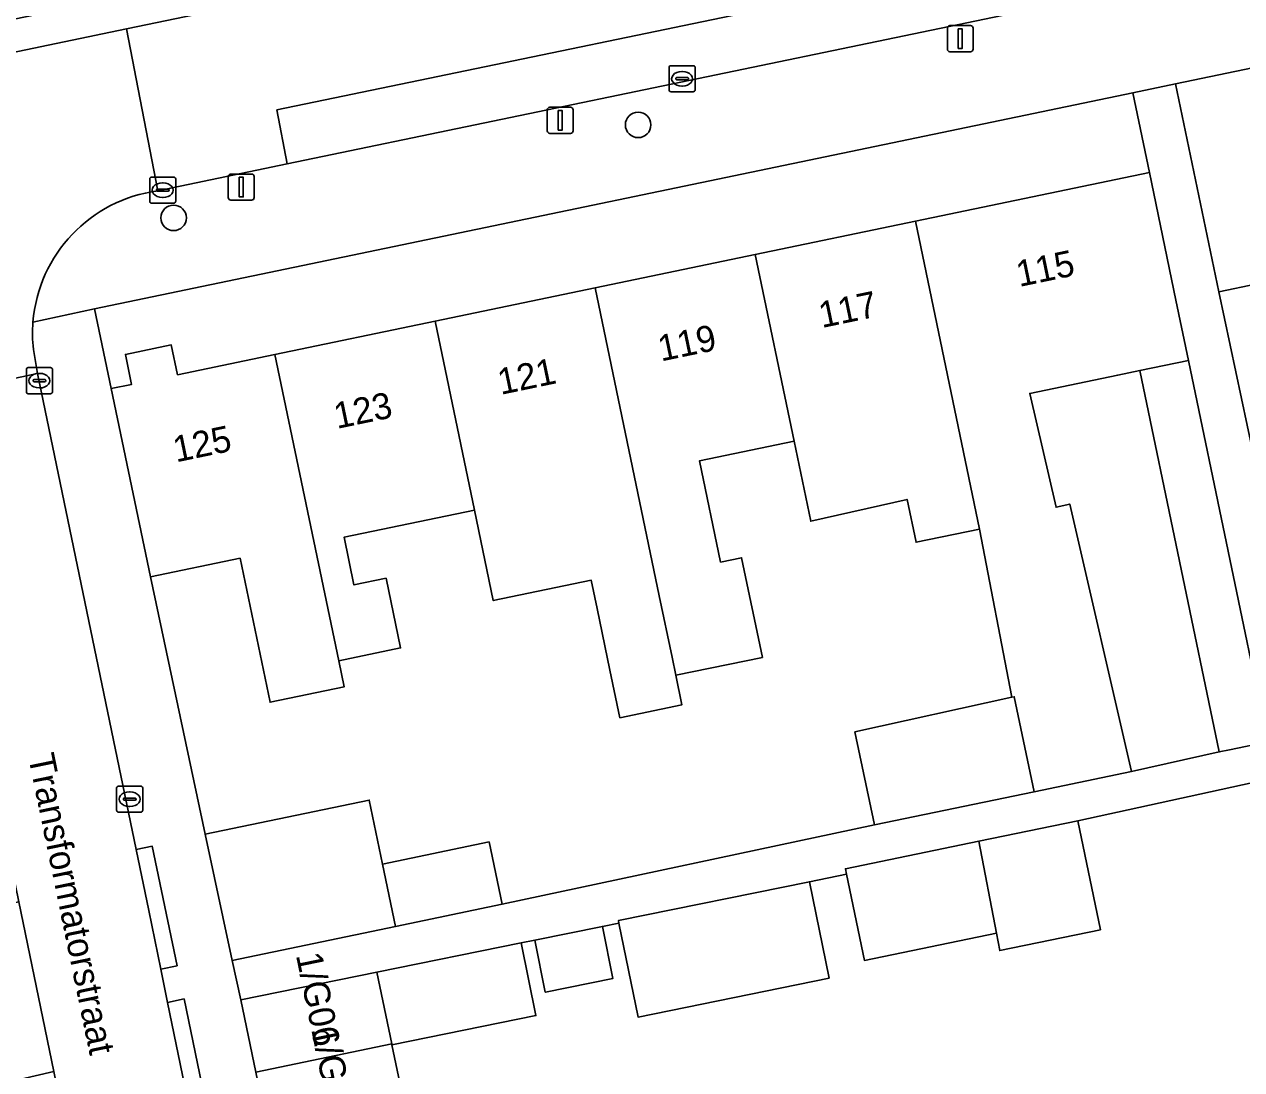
# Model space of a CAD drawing. Extents: x 162989 to 165008, y 383432 to 384338.
# Drawn here: x 163580.92 to 163627.57, y 384033.07 to 384073.15 of the extents above; entities that cross this region are included whole.
import ezdxf

# ---------------------------------------------------------------- set-up
doc = ezdxf.new("R2010")
doc.units = 0
for name, color, linetype in [('IMGEO_Boom', 7, 'Continuous'), ('IMGEO_Erf', 7, 'Continuous'), ('IMGEO_Groenvoorziening', 7, 'Continuous'), ('IMGEO_Kolk', 7, 'Continuous'), ('IMGEO_Lichtmast', 7, 'Continuous'), ('IMGEO_Muur', 7, 'Continuous'), ('IMGEO_Openbare_ruimte_label', 7, 'Continuous'), ('IMGEO_Pand', 7, 'Continuous'), ('IMGEO_Pand_nummerreeks', 7, 'Continuous'), ('IMGEO_Parkeervlak_gesloten', 7, 'Continuous'), ('IMGEO_Rijbaan_lokaal_gesloten', 7, 'Continuous'), ('IMGEO_Rijbaan_lokaal_open', 7, 'Continuous'), ('IMGEO_Voetpad_open', 7, 'Continuous')]:
    doc.layers.add(name, color=color, linetype=linetype)

msp = doc.modelspace()

# ---------------------------------------------------------------- linework, layer by layer
at = {"layer": 'IMGEO_Boom'}
for centre in [(163604.444, 384069.294), (163586.64, 384065.728)]:
    msp.add_circle(centre, 0.489, dxfattribs=at)
at = {"layer": 'IMGEO_Erf'}
for points in [[(163659.843, 384072.857), (163662.816, 384073.476), (163662.616, 384074.437), (163665.063, 384074.949), (163665.263, 384073.985), (163666.126, 384074.165), (163666.339, 384073.14), (163669.273, 384073.751), (163668.011, 384079.81), (163625.04, 384070.863), (163626.7, 384062.893), (163629.637, 384063.504), (163629.026, 384066.441), (163635.305, 384067.748), (163641.439, 384069.025), (163642.135, 384069.17), (163641.933, 384070.139), (163644.293, 384070.631), (163644.494, 384069.661), (163647.574, 384070.303), (163653.707, 384071.579)], [(163623.4, 384070.522), (163583.605, 384062.236), (163584.246, 384059.183), (163585.029, 384059.346), (163584.791, 384060.491), (163586.553, 384060.858), (163586.791, 384059.713), (163590.526, 384060.49), (163596.662, 384061.768), (163602.797, 384063.045), (163608.933, 384064.322), (163615.068, 384065.599), (163624.036, 384067.466)], [(163623.669, 384059.875), (163622.828, 384059.7), (163619.451, 384058.997), (163620.46, 384054.633), (163620.987, 384054.754), (163623.355, 384044.505), (163626.714, 384045.25)], [(163602.873, 384050.747), (163602.646, 384051.837), (163598.891, 384051.056), (163598.17, 384054.521), (163593.174, 384053.481), (163593.554, 384051.653), (163594.785, 384051.909), (163595.341, 384049.239), (163592.972, 384048.744), (163593.179, 384047.749), (163590.336, 384047.157), (163589.186, 384052.68), (163585.749, 384051.964), (163587.856, 384042.101), (163594.14, 384043.409), (163594.652, 384040.952), (163598.731, 384041.801), (163599.228, 384039.412), (163613.497, 384042.453), (163612.754, 384046.021), (163618.763, 384047.349), (163617.523, 384053.796), (163615.094, 384053.291), (163614.752, 384054.934), (163611.06, 384054.099), (163610.421, 384057.17), (163606.798, 384056.416), (163607.606, 384052.532), (163608.411, 384052.699), (163609.206, 384048.879), (163605.887, 384048.189), (163606.122, 384047.059), (163603.743, 384046.564), (163603.363, 384048.389)]]:
    msp.add_lwpolyline(points, close=True, dxfattribs=at)
msp.add_lwpolyline([(163629.536, 384044.408), (163621.297, 384042.615), (163622.161, 384038.437), (163618.3, 384037.633), (163618.172, 384038.306), (163613.117, 384037.26), (163612.432, 384040.571), (163611.007, 384040.276), (163611.76, 384036.579), (163604.439, 384035.087), (163603.705, 384038.688), (163603.073, 384038.559), (163603.477, 384036.571), (163600.895, 384036.046), (163600.884, 384036.044), (163600.48, 384038.032), (163599.962, 384037.927), (163600.527, 384035.142), (163595.008, 384034.021), (163595.573, 384031.285)], dxfattribs=at)
at = {"layer": 'IMGEO_Groenvoorziening'}
msp.add_lwpolyline([(163830.895, 384125.387), (163651.736, 384088.019), (163459.771, 384048.486), (163422.158, 384040.849), (163419.713, 384040.294), (163409.522, 384037.258), (163408.734, 384037.023), (163409.808, 384036.105), (163410.773, 384036.455), (163412.582, 384037.103), (163414.405, 384037.712), (163416.239, 384038.284), (163418.085, 384038.817), (163419.942, 384039.312), (163421.809, 384039.768), (163423.331, 384040.11), (163470.865, 384049.76), (163474.78, 384050.554), (163569.015, 384069.685), (163584.838, 384072.976), (163644.593, 384085.348), (163648.507, 384086.167), (163682.411, 384093.294), (163707.965, 384098.574)], dxfattribs=at)
at = {"layer": 'IMGEO_Kolk'}
for p, q in [((163605.629, 384070.638), (163605.629, 384071.49)), ((163605.704, 384071.564), (163606.556, 384071.564)), ((163606.117, 384071.344), (163606.142, 384071.344)), ((163606.63, 384071.49), (163606.63, 384070.638)), ((163605.888, 384071.058), (163605.888, 384071.07)), ((163606.326, 384071.021), (163605.928, 384071.021)), ((163605.931, 384071.107), (163606.329, 384071.107)), ((163606.14, 384070.784), (163606.115, 384070.784)), ((163606.372, 384071.07), (163606.372, 384071.058)), ((163606.556, 384070.564), (163605.704, 384070.564)), ((163585.724, 384066.366), (163585.724, 384067.218)), ((163585.799, 384067.292), (163586.651, 384067.292)), ((163586.212, 384067.072), (163586.237, 384067.072)), ((163586.725, 384067.218), (163586.725, 384066.366)), ((163585.983, 384066.786), (163585.983, 384066.798)), ((163586.421, 384066.749), (163586.023, 384066.749)), ((163586.026, 384066.835), (163586.424, 384066.835)), ((163586.235, 384066.512), (163586.21, 384066.512)), ((163586.467, 384066.798), (163586.467, 384066.786)), ((163586.651, 384066.292), (163585.799, 384066.292)), ((163581.073, 384059.988), (163581.925, 384059.988)), ((163580.998, 384059.062), (163580.998, 384059.914)), ((163581.257, 384059.482), (163581.257, 384059.494)), ((163581.3, 384059.531), (163581.698, 384059.531)), ((163581.486, 384059.768), (163581.511, 384059.768)), ((163581.741, 384059.494), (163581.741, 384059.482)), ((163581.999, 384059.914), (163581.999, 384059.062)), ((163581.695, 384059.445), (163581.297, 384059.445)), ((163581.509, 384059.208), (163581.484, 384059.208)), ((163581.925, 384058.988), (163581.073, 384058.988)), ((163584.457, 384043.016), (163584.457, 384043.868)), ((163584.532, 384043.942), (163585.384, 384043.942)), ((163584.945, 384043.722), (163584.97, 384043.722)), ((163585.458, 384043.868), (163585.458, 384043.016)), ((163584.716, 384043.436), (163584.716, 384043.448)), ((163585.154, 384043.399), (163584.756, 384043.399)), ((163584.759, 384043.485), (163585.157, 384043.485)), ((163585.2, 384043.448), (163585.2, 384043.436)), ((163585.384, 384042.942), (163584.532, 384042.942)), ((163584.968, 384043.162), (163584.943, 384043.162))]:
    msp.add_line(p, q, dxfattribs=at)
for points in [[(163605.629, 384070.638), (163605.629, 384071.49)], [(163605.704, 384071.564), (163606.556, 384071.564)], [(163606.63, 384071.49), (163606.63, 384070.638)], [(163606.556, 384070.564), (163605.704, 384070.564)], [(163585.724, 384066.366), (163585.724, 384067.218)], [(163585.799, 384067.292), (163586.651, 384067.292)], [(163586.725, 384067.218), (163586.725, 384066.366)], [(163586.651, 384066.292), (163585.799, 384066.292)], [(163581.073, 384059.988), (163581.925, 384059.988)], [(163580.998, 384059.062), (163580.998, 384059.914)], [(163581.999, 384059.914), (163581.999, 384059.062)], [(163581.925, 384058.988), (163581.073, 384058.988)], [(163584.457, 384043.016), (163584.457, 384043.868)], [(163584.532, 384043.942), (163585.384, 384043.942)], [(163585.458, 384043.868), (163585.458, 384043.016)], [(163585.384, 384042.942), (163584.532, 384042.942)]]:
    msp.add_lwpolyline(points, dxfattribs=at)
for centre, radius, start, end in [((163605.706, 384071.488), 0.0765, 91.552, 178.448), ((163605.706, 384071.488), 0.0765, 91.552, 178.448), ((163606.554, 384071.488), 0.0765, 1.552, 88.448), ((163606.554, 384071.488), 0.0765, 1.552, 88.448), ((163605.928, 384071.067), 0.0403, 85.8775, 175.7526), ((163605.925, 384071.057), 0.0366, 178.938, 274.7102), ((163606.329, 384071.064), 0.043, 264.8664, 352.4533), ((163606.333, 384071.069), 0.0386, 1.7309, 96.639), ((163605.706, 384070.64), 0.0765, 181.552, 268.448), ((163605.706, 384070.64), 0.0765, 181.552, 268.448), ((163606.554, 384070.64), 0.0765, 271.552, 358.448), ((163606.554, 384070.64), 0.0765, 271.552, 358.448), ((163585.801, 384067.216), 0.0765, 91.552, 178.448), ((163585.801, 384067.216), 0.0765, 91.552, 178.448), ((163586.649, 384067.216), 0.0765, 1.552, 88.448), ((163586.649, 384067.216), 0.0765, 1.552, 88.448), ((163586.023, 384066.795), 0.0403, 85.8775, 175.7526), ((163586.02, 384066.785), 0.0366, 178.938, 274.7102), ((163586.424, 384066.792), 0.043, 264.8664, 352.4533), ((163586.428, 384066.797), 0.0386, 1.7309, 96.639), ((163585.801, 384066.368), 0.0765, 181.552, 268.448), ((163585.801, 384066.368), 0.0765, 181.552, 268.448), ((163586.649, 384066.368), 0.0765, 271.552, 358.448), ((163586.649, 384066.368), 0.0765, 271.552, 358.448), ((163581.075, 384059.912), 0.0765, 91.552, 178.448), ((163581.075, 384059.912), 0.0765, 91.552, 178.448), ((163581.923, 384059.912), 0.0765, 1.552, 88.448), ((163581.923, 384059.912), 0.0765, 1.552, 88.448), ((163581.297, 384059.491), 0.0403, 85.8775, 175.7526), ((163581.702, 384059.493), 0.0386, 1.7309, 96.639), ((163581.075, 384059.064), 0.0765, 181.552, 268.448), ((163581.075, 384059.064), 0.0765, 181.552, 268.448), ((163581.294, 384059.481), 0.0366, 178.938, 274.7102), ((163581.698, 384059.488), 0.043, 264.8664, 352.4533), ((163581.923, 384059.064), 0.0765, 271.552, 358.448), ((163581.923, 384059.064), 0.0765, 271.552, 358.448), ((163584.534, 384043.866), 0.0765, 91.552, 178.448), ((163584.534, 384043.866), 0.0765, 91.552, 178.448), ((163585.382, 384043.866), 0.0765, 1.552, 88.448), ((163585.382, 384043.866), 0.0765, 1.552, 88.448), ((163584.756, 384043.445), 0.0403, 85.8775, 175.7526), ((163584.753, 384043.435), 0.0366, 178.938, 274.7102), ((163585.157, 384043.442), 0.043, 264.8664, 352.4533), ((163585.161, 384043.447), 0.0386, 1.7309, 96.639), ((163584.534, 384043.018), 0.0765, 181.552, 268.448), ((163584.534, 384043.018), 0.0765, 181.552, 268.448), ((163585.382, 384043.018), 0.0765, 271.552, 358.448), ((163585.382, 384043.018), 0.0765, 271.552, 358.448)]:
    msp.add_arc(centre, radius, start, end, dxfattribs=at)
for centre, major_axis, ratio, start_param, end_param in [((163606.116, 384071.064), (-0.387, 0.002), 0.722429, 4.712389, 7.853982), ((163606.141, 384071.064), (-0.39, 0.002), 0.717154, 1.570796, 4.712389), ((163586.211, 384066.792), (-0.387, 0.002), 0.722429, 4.712389, 7.853982), ((163586.236, 384066.792), (-0.39, 0.002), 0.717154, 1.570796, 4.712389), ((163581.485, 384059.488), (-0.387, 0.002), 0.722429, 4.712389, 7.853982), ((163581.51, 384059.488), (-0.39, 0.002), 0.717154, 1.570796, 4.712389), ((163584.944, 384043.442), (-0.387, 0.002), 0.722429, 4.712389, 7.853982), ((163584.969, 384043.442), (-0.39, 0.002), 0.717154, 1.570796, 4.712389)]:
    msp.add_ellipse(centre, major_axis=major_axis, ratio=ratio, start_param=start_param, end_param=end_param, dxfattribs=at)
at = {"layer": 'IMGEO_Lichtmast'}
for p, q in [((163616.395, 384073.1), (163617.185, 384073.1)), ((163617.185, 384073.1), (163616.395, 384073.1)), ((163616.295, 384072.2), (163616.295, 384073)), ((163616.295, 384073), (163616.295, 384072.2)), ((163617.285, 384073), (163617.285, 384072.2)), ((163617.285, 384072.2), (163617.285, 384073)), ((163617.185, 384072.1), (163616.395, 384072.1)), ((163616.395, 384072.1), (163617.185, 384072.1)), ((163600.963, 384069.068), (163600.963, 384069.868)), ((163600.963, 384069.868), (163600.963, 384069.068)), ((163601.063, 384069.968), (163601.853, 384069.968)), ((163601.853, 384069.968), (163601.063, 384069.968)), ((163601.953, 384069.868), (163601.953, 384069.068)), ((163601.953, 384069.068), (163601.953, 384069.868)), ((163601.853, 384068.968), (163601.063, 384068.968)), ((163601.063, 384068.968), (163601.853, 384068.968)), ((163588.738, 384066.509), (163588.738, 384067.309)), ((163588.738, 384067.309), (163588.738, 384066.509)), ((163588.838, 384067.409), (163589.628, 384067.409)), ((163589.628, 384067.409), (163588.838, 384067.409)), ((163589.728, 384067.309), (163589.728, 384066.509)), ((163589.728, 384066.509), (163589.728, 384067.309)), ((163589.628, 384066.409), (163588.838, 384066.409)), ((163588.838, 384066.409), (163589.628, 384066.409))]:
    msp.add_line(p, q, dxfattribs=at)
for points in [[(163616.715, 384072.975), (163616.865, 384072.975), (163616.865, 384072.225), (163616.715, 384072.225), (163616.715, 384072.975)], [(163601.383, 384069.843), (163601.533, 384069.843), (163601.533, 384069.093), (163601.383, 384069.093), (163601.383, 384069.843)], [(163589.158, 384067.284), (163589.308, 384067.284), (163589.308, 384066.534), (163589.158, 384066.534), (163589.158, 384067.284)]]:
    msp.add_lwpolyline(points, dxfattribs=at)
for centre, start, end in [((163616.395, 384073), 90, 180), ((163616.395, 384073), 90, 180), ((163617.185, 384073), 0, 90), ((163617.185, 384073), 360, 90), ((163616.395, 384072.2), 180, 270), ((163616.395, 384072.2), 180, 270), ((163617.185, 384072.2), 270, 0), ((163617.185, 384072.2), 270, 0), ((163601.063, 384069.868), 90, 180), ((163601.063, 384069.868), 90, 180), ((163601.853, 384069.868), 0, 90), ((163601.853, 384069.868), 360, 90), ((163601.063, 384069.068), 180, 270), ((163601.063, 384069.068), 180, 270), ((163601.853, 384069.068), 270, 0), ((163601.853, 384069.068), 270, 0), ((163588.838, 384067.309), 90, 180), ((163588.838, 384067.309), 90, 180), ((163589.628, 384067.309), 0, 90), ((163589.628, 384067.309), 360, 90), ((163588.838, 384066.509), 180, 270), ((163588.838, 384066.509), 180, 270), ((163589.628, 384066.509), 270, 0), ((163589.628, 384066.509), 270, 0)]:
    msp.add_arc(centre, 0.1, start, end, dxfattribs=at)
at = {"layer": 'IMGEO_Muur'}
msp.add_lwpolyline([(163585.749, 384051.964), (163587.856, 384042.101)], dxfattribs=at)
at = {"layer": 'IMGEO_Pand'}
for points in [[(163625.055, 384062.571), (163624.036, 384067.466), (163615.068, 384065.599), (163617.523, 384053.796), (163618.763, 384047.349), (163618.859, 384047.37), (163619.617, 384043.727), (163623.355, 384044.505), (163620.987, 384054.754), (163620.46, 384054.633), (163619.451, 384058.997), (163622.828, 384059.7), (163623.669, 384059.875), (163625.535, 384060.264)], [(163635.305, 384067.748), (163629.026, 384066.441), (163629.637, 384063.504), (163626.7, 384062.893), (163628.216, 384055.732), (163634.948, 384057.032), (163635.285, 384055.287), (163637.792, 384055.812)], [(163608.933, 384064.322), (163610.421, 384057.17), (163611.06, 384054.099), (163614.752, 384054.934), (163615.094, 384053.291), (163617.523, 384053.796), (163615.068, 384065.599)], [(163608.933, 384064.322), (163602.797, 384063.045), (163605.252, 384051.242), (163605.742, 384048.884), (163605.887, 384048.189), (163609.206, 384048.879), (163608.411, 384052.699), (163607.606, 384052.532), (163606.798, 384056.416), (163610.421, 384057.17)], [(163602.797, 384063.045), (163596.662, 384061.768), (163598.17, 384054.521), (163598.891, 384051.056), (163602.646, 384051.837), (163602.873, 384050.747), (163603.363, 384048.389), (163603.743, 384046.564), (163606.122, 384047.059), (163605.887, 384048.189), (163605.742, 384048.884), (163605.252, 384051.242)], [(163598.17, 384054.521), (163596.662, 384061.768), (163590.526, 384060.49), (163592.972, 384048.744), (163595.341, 384049.239), (163594.785, 384051.909), (163593.554, 384051.653), (163593.174, 384053.481)], [(163590.526, 384060.49), (163586.791, 384059.713), (163586.553, 384060.858), (163584.791, 384060.491), (163585.029, 384059.346), (163584.246, 384059.183), (163585.749, 384051.964), (163589.186, 384052.68), (163590.336, 384047.157), (163593.179, 384047.749), (163592.972, 384048.744)], [(163625.535, 384060.264), (163623.669, 384059.875), (163626.714, 384045.25), (163627.112, 384045.333), (163628.58, 384045.639)], [(163618.763, 384047.349), (163612.754, 384046.021), (163613.497, 384042.453), (163619.617, 384043.727), (163618.859, 384047.37)], [(163594.652, 384040.952), (163594.14, 384043.409), (163587.856, 384042.101), (163588.889, 384037.26), (163595.149, 384038.563)], [(163617.505, 384041.831), (163618.172, 384038.306), (163618.3, 384037.633), (163622.161, 384038.437), (163621.297, 384042.615)], [(163594.652, 384040.952), (163595.149, 384038.563), (163599.228, 384039.412), (163598.731, 384041.801)], [(163617.505, 384041.831), (163612.39, 384040.773), (163612.432, 384040.571), (163613.117, 384037.26), (163618.172, 384038.306)], [(163611.007, 384040.276), (163603.686, 384038.783), (163603.705, 384038.688), (163604.439, 384035.087), (163611.76, 384036.579)], [(163600.884, 384036.044), (163600.895, 384036.046), (163603.477, 384036.571), (163603.073, 384038.559), (163600.48, 384038.032)], [(163599.962, 384037.927), (163594.432, 384036.803), (163595.001, 384034.054), (163595.008, 384034.021), (163600.527, 384035.142)], [(163589.788, 384032.973), (163595.001, 384034.054), (163594.432, 384036.803), (163589.214, 384035.741)], [(163595.008, 384034.021), (163595.001, 384034.054), (163589.788, 384032.973), (163590.362, 384030.204), (163595.573, 384031.285)]]:
    msp.add_lwpolyline(points, close=True, dxfattribs=at)
at = {"layer": 'IMGEO_Parkeervlak_gesloten'}
msp.add_lwpolyline([(163622.519, 384074.351), (163622.098, 384076.374), (163614.905, 384074.918), (163590.6, 384069.869), (163590.992, 384067.795)], close=True, dxfattribs=at)
at = {"layer": 'IMGEO_Rijbaan_lokaal_gesloten'}
msp.add_lwpolyline([(163622.519, 384074.351), (163624.166, 384074.693), (163627.245, 384075.333), (163628.582, 384075.611), (163628.228, 384077.661), (163645.447, 384081.238), (163644.593, 384085.348), (163584.838, 384072.976), (163586.035, 384066.764), (163590.992, 384067.795), (163590.6, 384069.869), (163614.905, 384074.918), (163622.098, 384076.374)], close=True, dxfattribs=at)
at = {"layer": 'IMGEO_Rijbaan_lokaal_open'}
for points in [[(163586.035, 384066.764), (163584.838, 384072.976), (163569.015, 384069.685), (163570.204, 384063.489), (163571.591, 384063.591)], [(163576.771, 384058.775), (163581.425, 384059.764), (163581.267, 384060.688)], [(163586.411, 384035.65), (163586.148, 384036.924), (163585.686, 384039.167), (163585.202, 384041.508), (163581.425, 384059.764), (163576.771, 384058.775), (163578.473, 384050.415), (163580.713, 384039.503), (163582.049, 384032.997), (163584.746, 384019.857), (163584.891, 384019.151), (163586.202, 384012.873), (163586.482, 384011.534), (163587.727, 384005.569), (163587.95, 384004.503)], [(163590.997, 384013.484), (163590.006, 384018.235), (163589.539, 384020.474), (163586.411, 384035.65)]]:
    msp.add_lwpolyline(points, dxfattribs=at)
for centre, radius, start, end in [((163586.752, 384061.293), 5.518, 97.4671, 175.4166), ((163586.611, 384061.288), 5.378, 175.24, 186.4032)]:
    msp.add_arc(centre, radius, start, end, dxfattribs=at)
at = {"layer": 'IMGEO_Voetpad_open'}
for points in [[(163709.326, 384092.401), (163702.134, 384090.906), (163673.753, 384085.004), (163671.946, 384084.628), (163672.022, 384084.243), (163668.293, 384083.466), (163668.213, 384083.852), (163667.235, 384083.649), (163667.315, 384083.262), (163664.069, 384082.586), (163663.989, 384082.974), (163661.839, 384082.527), (163649.811, 384080.025), (163645.869, 384079.206), (163628.582, 384075.611), (163627.245, 384075.333), (163627.329, 384074.93), (163624.254, 384074.289), (163624.166, 384074.693), (163622.519, 384074.351), (163590.992, 384067.795), (163586.035, 384066.764)], [(163581.252, 384061.734), (163583.605, 384062.236), (163623.4, 384070.522), (163625.04, 384070.863), (163668.011, 384079.81)], [(163628.216, 384055.732), (163626.7, 384062.893), (163625.04, 384070.863), (163623.4, 384070.522), (163624.036, 384067.466), (163625.055, 384062.571), (163625.535, 384060.264), (163628.58, 384045.639), (163627.112, 384045.333), (163626.714, 384045.25), (163623.355, 384044.505), (163619.617, 384043.727), (163613.497, 384042.453), (163599.228, 384039.412), (163595.149, 384038.563), (163588.889, 384037.26), (163589.214, 384035.741), (163594.432, 384036.803), (163599.962, 384037.927), (163600.48, 384038.032), (163603.073, 384038.559), (163603.705, 384038.688), (163603.686, 384038.783), (163611.007, 384040.276), (163612.432, 384040.571), (163612.39, 384040.773), (163617.505, 384041.831), (163621.297, 384042.615), (163629.536, 384044.408)], [(163589.788, 384032.973), (163589.214, 384035.741), (163588.889, 384037.26), (163587.856, 384042.101), (163585.749, 384051.964), (163584.246, 384059.183), (163583.605, 384062.236), (163581.252, 384061.734)], [(163581.267, 384060.688), (163581.425, 384059.764), (163585.202, 384041.508), (163585.822, 384041.636), (163586.776, 384037.054), (163586.148, 384036.924), (163586.411, 384035.65), (163587.04, 384035.78), (163590.638, 384018.366), (163590.006, 384018.235), (163590.997, 384013.484)]]:
    msp.add_lwpolyline(points, dxfattribs=at)
for points in [[(163585.822, 384041.636), (163585.202, 384041.508), (163585.686, 384039.167), (163586.148, 384036.924), (163586.776, 384037.054)], [(163580.713, 384039.503), (163578.307, 384039.001), (163579.019, 384035.588), (163579.672, 384032.452), (163582.049, 384032.997)], [(163587.04, 384035.78), (163586.411, 384035.65), (163589.539, 384020.474), (163590.006, 384018.235), (163590.638, 384018.366)]]:
    msp.add_lwpolyline(points, close=True, dxfattribs=at)
for centre, radius, start, end in [((163586.752, 384061.293), 5.518, 97.4671, 175.4166), ((163586.611, 384061.288), 5.378, 175.24, 186.4032)]:
    msp.add_arc(centre, radius, start, end, dxfattribs=at)

# ---------------------------------------------------------------- texts
at = {"layer": 'IMGEO_Openbare_ruimte_label'}
msp.add_text('Transformatorstraat', height=1, rotation=281.6584, dxfattribs=at).set_placement((163581.063, 384045.083))
at = {"layer": 'IMGEO_Pand_nummerreeks'}
for s, rotation, p in [('115', 11.7571, (163619.051, 384063.078)), ('117', 11.7592, (163611.484, 384061.503)), ('119', 11.7571, (163605.321, 384060.22)), ('121', 11.7571, (163599.178, 384058.941)), ('123', 11.7592, (163592.901, 384057.635)), ('125', 11.7571, (163586.737, 384056.351)), ('1/G06', 281.6385, (163591.326, 384037.463)), ('1/G05', 281.6366, (163591.912, 384034.619))]:
    msp.add_text(s, height=1, rotation=rotation, dxfattribs=at).set_placement(p)

doc.saveas('drawing.dxf')
